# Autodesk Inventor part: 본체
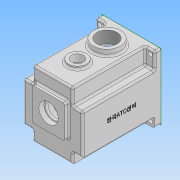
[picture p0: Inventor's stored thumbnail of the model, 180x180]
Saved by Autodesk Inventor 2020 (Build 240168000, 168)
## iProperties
Created: 2022-01
Part Number: 본체
Material: 일반
Document SubType Name: Modeling
Designer: user
Density: 1 g/cm^3
Appearance: 기본값
Author: user
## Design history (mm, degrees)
sketch "스케치1"
  geometry: L1 (-49, -55)-(49, -55); L2 (49, -55)-(49, 55); L3 (49, 55)-(-49, 55); L4 (-49, 55)-(-49, -55); L5 (-49, -55)-(49, 55); L6 (49, -55)-(-49, 55); 1 further point
  constraints: 12 end point, 2 midpoint, 2 parallel, 1 horizontal, 1 perpendicular
  dimensions: "d0" = 98 distance of L3.end L2.end; "d1" = 110 distance of L2.end L1.end
extrude "돌출1" new body sketch "스케치1" distance "d2" = 130; taper "d3" = 0 deg
sketch "스케치2"
  geometry: L1 (-49, -55)-(49, -55) reference; L2 (-27, -21)-(27, -21); L3 (27, -21)-(27, 33); L4 (27, 33)-(-27, 33); L5 (-27, 33)-(-27, -21); L6 (-27, -21)-(27, 33); L7 (27, -21)-(-27, 33); 3 further points
  constraints: 12 end point, 3 midpoint, 2 parallel, 1 horizontal, 1 perpendicular, 1 vertical alignment
  dimensions: "d4" = 54 distance of L3.end L4.end; "d5" = 54 distance of L2.end L3.end; "d7" = 61 distance from line of point (0, 6) L1
extrude "돌출2" join sketch "스케치2" distance "d8" = 7; taper "d9" = 0 deg
sketch "스케치3"
  geometry: L1 (27, 33)-(27, -21) reference; L2 (27, -21)-(-27, -21) reference; L3 (-27, -21)-(-27, 33) reference; L4 (-27, 33)-(27, 33) reference; L5 (-49, -55)-(49, -55) reference; L6 (49, -55)-(49, 55) reference; L7 (49, 55)-(-49, 55) reference; L8 (-49, 55)-(-49, -55) reference; L9 (-49, 55)-(-33, 55); L10 (-33, 55)-(-33, 28); L11 (-33, 28)-(-49, 28); L12 (-49, 28)-(-49, 55); L13 (49, 55)-(33, 55); L14 (33, 55)-(33, 28); L15 (33, 28)-(49, 28); L16 (49, 28)-(49, 55); L17 (-49, -55)-(-33, -55); L18 (-33, -55)-(-33, -38); L19 (-33, -38)-(-49, -38); L20 (-49, -38)-(-49, -55); L21 (49, -55)-(33, -55); L22 (33, -55)-(33, -38); L23 (33, -38)-(49, -38); L24 (49, -38)-(49, -55); 9 further points
  constraints: 32 end point, 8 parallel, 4 horizontal, 4 perpendicular, 1 horizontal alignment, 1 point on line
  dimensions: "d10" = 16 distance of L7.end L9.end; "d11" = 16 distance of L6.end L13.end; "d12" = 16 distance between parallel lines of L8 L18; "d13" = 16 distance between parallel lines of L6 L22; "d14" = 27 distance between parallel lines of L11 L7; "d15" = 17 distance between parallel lines of L19 L5
extrude "돌출3" cut sketch "스케치3" distance "d16" = 120; taper "d17" = 0 deg
sketch "스케치4"
  geometry: L1 (-49, -55)-(49, -55) reference; L2 (-23, 45)-(23, 45); L3 (23, 45)-(23, 30.143); L4 (-23, 30.143)-(-23, 45); A1 r 42 centre (0, -5) between (-23, 30.143) and (23, 30.143); 4 further points
  constraints: 6 end point, 2 point on circle, 2 vertical alignment, 1 centre point, 1 horizontal, 1 midpoint, 1 parallel, 1 perpendicular
  dimensions: "d18" = 50 distance from line of A1.centre L1; "d19" = 84 diameter of A1; "d20" = 50 distance from line of A1.centre L2; "d21" = 46 distance of L2.start L2.end
extrude "돌출4" cut sketch "스케치4" distance "d22" = 121; taper "d23" = 0 deg
sketch "스케치5"
  geometry: L1 (23, 45)-(23, 30.143) reference; L2 (-23, 30.143)-(-23, 45) reference; L3 (-23, 45)-(23, 45) reference; L4 (26, 31.729)-(26, 48); L5 (26, 48)-(-26, 48); L6 (-26, 48)-(-26, 31.729); A1 r 42 centre (0, -5) between (-23, 30.143) and (23, 30.143) reference; A2 r 45 centre (0, -5) between (-26, 31.729) and (26, 31.729); 1 further point
  constraints: 6 end point, 2 point on circle, 1 centre point, 3 other
  dimensions: "d24" = 3 radial gap between concentric circles of A1 A2
extrude "돌출5" cut sketch "스케치5" distance "d25" = 9; taper "d26" = 0 deg
sketch "스케치6"
  geometry: C1 r 21 at (0, 6); C2 r 15 at (0, -25); A1 r 42 centre (0, -5) between (-23, 30.143) and (23, 30.143) reference; 3 further points
  constraints: 2 centre point, 2 vertical alignment
  dimensions: "d27" = 20 distance of C2.centre A1.centre; "d28" = 11 distance of A1.centre C1.centre; "d29" = 42 diameter of C1; "d30" = 30 diameter of C2
extrude "돌출6" join sketch "스케치6" distance "d31" = 7; taper "d32" = 0 deg
sketch "스케치7"
  geometry: A1 r 15 centre (0, -25) between (-8.978, -12.984) and (8.978, -12.984) reference; 1 further point
hole "구멍1" sketch "스케치7" at (0, -25) diameter "d33" = 19; stored, may be unused: countersink angle "d37" = 90 deg, drill point angle "d39" = 0 deg; dims "d34" = 70, "d35" = 22, "d36" = 7, "d38" = 10
sketch "스케치8"
  geometry: A1 r 21 centre (0, 6) between (8.978, -12.984) and (-8.978, -12.984) reference; 2 further points
  constraints: 1 coincident
hole "구멍2" sketch "스케치8" at (0, 6) diameter "d40" = 28; stored, may be unused: countersink angle "d44" = 90 deg, drill point angle "d46" = 0 deg; dims "d41" = 70, "d42" = 35, "d43" = 10, "d45" = 10
sketch "스케치9"
  geometry: C1 r 14 at (0, 6) reference; C2 r 16 at (0, 6); 1 further point
  constraints: 1 centre point, 1 coincident
  dimensions: "d47" = 32 diameter of C2
extrude "돌출7" cut sketch "스케치9" distance "d48" = 8.3; taper "d49" = 0 deg
sketch "스케치10"
  geometry: L1 (-36, -1)-(-41.809, -1); L2 (-36, -9)-(-41.809, -9); A1 r 45 centre (0, -5) between (-26, 31.729) and (26, 31.729) reference; A2 r 42 centre (0, -5) between (-23, 30.143) and (23, 30.143) reference; A3 r 4 centre (-36, -5) between (-36, -1) and (-36, -9); A4 r 42 centre (0, -5) between (-23, 30.143) and (23, 30.143) reference; 3 further points
  constraints: 4 end point, 4 point on circle, 2 horizontal, 2 tangent, 1 centre point, 1 horizontal alignment
  dimensions: "d50" = 8 diameter of A3; "d51" = 36 distance of A3.centre A1.centre
extrude "돌출8" join sketch "스케치10" stored distance "d52" = 8.3; taper "d53" = 0 deg
sketch "스케치11"
  geometry: L1 (98, 0)-(0, 0) reference; L2 (49, 0)-(49, -40); L3 (49, -40)-(49, -89); C1 r 22.5 at (49, -40); C2 r 15 at (49, -89); 1 further point
  constraints: 4 end point, 2 centre point, 2 coincident, 1 midpoint, 1 point on line, 1 vertical
  dimensions: "d66" = 40 distance of L2.start L2.end; "d67" = 49 distance of L2.end L3.end; "d68" = 45 diameter of C1; "d69" = 30 diameter of C2
sketch "스케치12"
  geometry: L1 (-26, 48)-(26, 48) reference; L2 (-49, 55)-(-49, -55) reference; L3 (-49, 55)-(-49, 48); L4 (-49, 48)-(-42, 48); L5 (-42, 48)-(42, 48); L6 (42, 48)-(42, -48); L7 (42, -48)-(-42, -48); L8 (-42, -48)-(-42, 48); 1 further point
  constraints: 12 end point, 2 perpendicular, 2 point on line, 1 horizontal
  dimensions: "d54" = 7 distance of L2.start L3.end; "d55" = 7 distance of L3.end L4.end; "d56" = 84 distance of L4.end L5.end; "d57" = 96 distance of L5.end L6.end; "d58" = 84 distance of L6.end L7.end
hole "구멍3" sketch "스케치12" at (-42, 48), (-42, -48), (42, -48), (42, 48) diameter "d59" = 7; stored, may be unused: countersink angle "d63" = 90 deg, drill point angle "d65" = 0 deg; dims "d60" = 70, "d61" = 35, "d62" = 10, "d64" = 10
extrude "돌출9" join sketch "스케치11" distance "d70" = 10; taper "d71" = 0 deg
extrude "돌출10" join sketch "스케치11" distance "d72" = 5; taper "d73" = 0 deg
sketch "스케치13"
  geometry: C1 r 22.5 at (0, 0) reference; 2 further points
  constraints: 1 coincident
hole "구멍4" sketch "스케치13" at (0, 0) diameter "d74" = 33.376; stored, may be unused: countersink angle "d78" = 90 deg, drill point angle "d80" = 118 deg; dims "d75" = 30, "d76" = 35, "d77" = 10, "d79" = 77.3
sketch "스케치14"
  geometry: L1 (-26, 31.729)-(-26, 48) reference; L2 (-26, 48)-(26, 48) reference; L3 (26, 48)-(26, 31.729) reference; L4 (-49, -55)-(49, -55) reference; L5 (49, -55)-(49, 55) reference; L6 (49, 55)-(-49, 55) reference; L7 (-49, 55)-(-49, -55) reference; C1 r 3.5 at (42, -48) reference; C2 r 3.5 at (-42, 48) reference; C3 r 3.5 at (-42, -48) reference; C4 r 3.5 at (42, 48) reference; A1 r 45 centre (0, -5) between (-26, 31.729) and (26, 31.729) reference; 1 further point
sketch "스케치15"
  geometry: C1 r 15 at (0, 0) reference; 2 further points
  constraints: 1 coincident
hole "구멍5" sketch "스케치15" at (0, 0) diameter "d81" = 20; stored, may be unused: countersink angle "d85" = 90 deg, drill point angle "d87" = 0 deg; dims "d82" = 30, "d83" = 35, "d84" = 10, "d86" = 12
sketch "스케치16"
  geometry: C1 r 10 at (0, 0) reference; 2 further points
  constraints: 1 coincident
hole "구멍6" sketch "스케치16" at (0, 0) diameter "d88" = 30; stored, may be unused: countersink angle "d92" = 90 deg, drill point angle "d94" = 0 deg; dims "d89" = 30, "d90" = 35, "d91" = 10, "d93" = 5
sketch "스케치17"
  geometry: A1 r 4 centre (-36, -5) between (-36, -9) and (-36, -1) reference; 2 further points
  constraints: 1 coincident
hole "구멍7" sketch "스케치17" at (-36, -5) diameter "d95" = 3.242; stored, may be unused: countersink angle "d99" = 90 deg, drill point angle "d101" = 118 deg; dims "d96" = 7, "d97" = 35, "d98" = 10, "d100" = 9
sketch "스케치18"
  geometry: A1 r 4 centre (36, -5) between (36, -1) and (36, -9) reference; 2 further points
  constraints: 1 coincident
hole "구멍8" sketch "스케치18" at (36, -5) diameter "d102" = 3.242; stored, may be unused: countersink angle "d106" = 90 deg, drill point angle "d108" = 118 deg; dims "d103" = 7, "d104" = 35, "d105" = 10, "d107" = 9
fillet "모깎기1" dims "d109" = 6
fillet "모깎기2" dims "d110" = 3
fillet "모깎기3" dims "d111" = 3
fillet "모깎기4" dims "d112" = 3
fillet "모깎기5" dims "d113" = 0.3
fillet "모깎기6" dims "d114" = 3
fillet "모깎기7" dims "d115" = 3
fillet "모깎기9" dims "d117" = 3
sketch "스케치19"
  geometry: L1 (-13, 80)-(-127, 80) reference; L2 (-130, 104)-(-130, 83) reference; 2 further points
  constraints: 1 other
  dimensions: "d118" = 65 distance from line of L2 point (-65, 47); "d119" = 33 distance from line of L1 point (-65, 47)
feature "엠보싱1" sketch "스케치19" dims "d120" = 0.5, "d121" = 0
chamfer "모따기1" distance "d122" = 1; stored, may be unused: second distance "d123" = 2, angle "d124" = 45 deg
fillet "모깎기10" dims "d125" = 3
fillet "모깎기11" dims "d126" = 3
fillet "모깎기12" dims "d127" = 3
chamfer "모따기2" distance "d128" = 1; stored, may be unused: second distance "d129" = 2, angle "d130" = 45 deg
fillet "모깎기13" dims "d131" = 3
node "솔리드1"
mirror "미러1"
feature "A9D066F2-1C7D-4E18-AEED-F7BC21143FA4" dims "d33" = 19, "d34" = 70, "d35" = 22, "d36" = 7, "d37" = 90 deg, "d38" = 10, "d39" = 0
